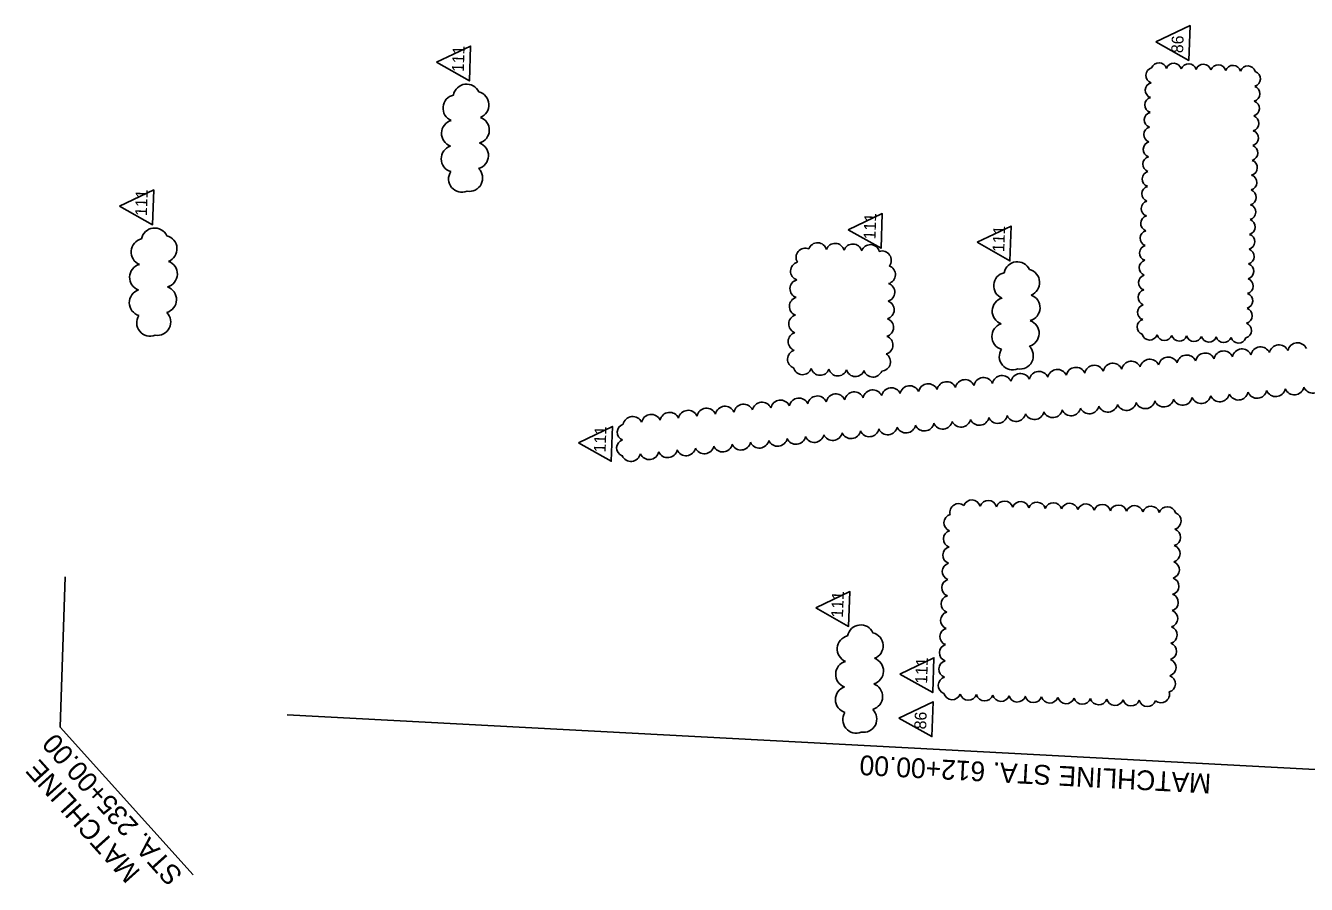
# Model space of a CAD drawing. Extents: x 928669 to 929521, y 636891 to 638153.
# Drawn here: x 928669 to 929187, y 636993 to 637341 of the extents above; entities that cross this region are included whole.
import ezdxf

# ---------------------------------------------------------------- set-up
doc = ezdxf.new("R2010")
doc.units = 0
doc.layers.add('Cloud_dp', color=7, linetype='Continuous')
doc.layers.add('MatchLines_dp', color=7, linetype='Continuous')

msp = doc.modelspace()

# ---------------------------------------------------------------- linework, layer by layer
at = {"layer": 'Cloud_dp'}
for points in [[(929126.34, 637333.99), (929139.65, 637326.48), (929140.14, 637340.55)], [(928835.21, 637325.69), (928848.52, 637318.18), (928849.01, 637332.25)], [(928706.97, 637267.46), (928720.28, 637259.95), (928720.77, 637274.02)], [(929001.81, 637257.92), (929015.12, 637250.41), (929015.62, 637264.49)], [(929053.95, 637252.83), (929067.26, 637245.32), (929067.75, 637259.4)], [(928892.62, 637171.72), (928905.92, 637164.21), (928906.42, 637178.28)], [(928988.69, 637104.86), (929001.99, 637097.34), (929002.49, 637111.42)], [(929022.71, 637078.07), (929036.02, 637070.56), (929036.51, 637084.63)], [(929022.35, 637060.26), (929035.66, 637052.75), (929036.15, 637066.82)]]:
    msp.add_lwpolyline(points, close=True, dxfattribs=at)
for centre, radius, start, end in [((929125.44, 637320.39), 3.15, 105.054, 250.054), ((929127.58, 637322.38), 3.14, 15.4978, 160.4978), ((929133.57, 637322.17), 3.14, 15.4978, 160.4978), ((929139.56, 637321.96), 3.14, 15.4978, 160.4978), ((929145.55, 637321.75), 3.14, 15.4978, 160.4978), ((929151.55, 637321.54), 3.14, 15.4978, 160.4978), ((929157.54, 637321.33), 3.14, 15.4978, 160.4978), ((929163.53, 637321.12), 3.14, 15.4978, 160.4978), ((929165.51, 637319), 3.14, 285.4978, 70.4978), ((928847.38, 637311.45), 5.42, 24.5019, 169.5019), ((929125.2, 637314.4), 3.14, 105.4978, 250.4978), ((928843.24, 637307.15), 5.42, 102.6495, 247.6495), ((928851.01, 637308.43), 5.42, 291.0688, 76.0688), ((929165.3, 637313), 3.14, 285.4978, 70.4978), ((929125, 637308.41), 3.14, 105.4978, 250.4978), ((929165.09, 637307.01), 3.14, 285.4978, 70.4978), ((928842.64, 637296.91), 5.42, 105.565, 250.565), ((928851.15, 637298.26), 5.42, 285.576, 70.576), ((929124.79, 637302.42), 3.14, 105.4978, 250.4978), ((929164.88, 637301.02), 3.14, 285.4978, 70.4978), ((929124.58, 637296.43), 3.14, 105.4978, 250.4978), ((929164.67, 637295.03), 3.14, 285.4978, 70.4978), ((928842.52, 637286.64), 5.42, 108.172, 253.172), ((928850.8, 637287.92), 5.42, 285.4978, 70.4978), ((929124.37, 637290.44), 3.14, 105.4978, 250.4978), ((929164.46, 637289.04), 3.14, 285.4978, 70.4978), ((929124.16, 637284.45), 3.14, 105.4978, 250.4978), ((929164.25, 637283.05), 3.14, 285.4978, 70.4978), ((928845.51, 637278.5), 5.42, 147.1328, 292.1328), ((928848.44, 637278.83), 5.42, 260.4905, 45.4905), ((929123.95, 637278.46), 3.14, 105.4978, 250.4978), ((929123.74, 637272.46), 3.14, 105.4978, 250.4978), ((929164.04, 637277.06), 3.14, 285.4978, 70.4978), ((929163.83, 637271.07), 3.14, 285.4978, 70.4978), ((929123.53, 637266.47), 3.14, 105.4978, 250.4978), ((929163.62, 637265.08), 3.14, 285.4978, 70.4978), ((929123.32, 637260.48), 3.14, 105.4978, 250.4978), ((929163.41, 637259.08), 3.14, 285.4978, 70.4978), ((928721.14, 637253.2), 5.42, 24.5019, 169.5019), ((928724.77, 637250.18), 5.42, 291.0688, 76.0688), ((929123.11, 637254.49), 3.14, 105.4978, 250.4978), ((929163.2, 637253.09), 3.14, 285.4978, 70.4978), ((928717.01, 637248.9), 5.42, 102.6495, 247.6495), ((928984.42, 637246.71), 3.74, 66.735, 211.735), ((928989.42, 637248.9), 3.74, 15.4978, 160.4978), ((928996.55, 637248.65), 3.74, 15.4978, 160.4978), ((929003.67, 637248.4), 3.74, 15.4978, 160.4978), ((929010.8, 637248.15), 3.74, 15.4978, 160.4978), ((929015.49, 637245.58), 3.74, 321.8977, 106.8977), ((929122.9, 637248.5), 3.14, 105.4978, 250.4978), ((929162.99, 637247.1), 3.14, 285.4978, 70.4978), ((928724.91, 637240.01), 5.42, 285.576, 70.576), ((928982.23, 637241.14), 3.74, 105.4978, 250.4978), ((929070.25, 637239.53), 5.42, 24.5019, 169.5019), ((929122.69, 637242.51), 3.14, 105.4978, 250.4978), ((928716.4, 637238.66), 5.42, 105.565, 250.565), ((929017.18, 637239.75), 3.74, 285.4978, 70.4978), ((929066.11, 637235.23), 5.42, 102.6495, 247.6495), ((929073.87, 637236.52), 5.42, 291.0688, 76.0688), ((929122.48, 637236.52), 3.14, 105.4978, 250.4978), ((929162.78, 637241.11), 3.14, 285.4978, 70.4978), ((928724.56, 637229.67), 5.42, 285.4978, 70.4978), ((928981.99, 637234.02), 3.74, 105.4978, 250.4978), ((929016.93, 637232.62), 3.74, 285.4978, 70.4978), ((929162.57, 637235.12), 3.14, 285.4978, 70.4978), ((928716.29, 637228.39), 5.42, 108.172, 253.172), ((928981.74, 637226.89), 3.74, 105.4978, 250.4978), ((929016.68, 637225.49), 3.74, 285.4978, 70.4978), ((929065.51, 637224.99), 5.42, 105.565, 250.565), ((929074.02, 637226.34), 5.42, 285.576, 70.576), ((929122.27, 637230.53), 3.14, 105.4978, 250.4978), ((929162.37, 637229.13), 3.14, 285.4978, 70.4978), ((928722.21, 637220.58), 5.42, 260.4905, 45.4905), ((929122.06, 637224.53), 3.14, 105.4978, 250.4978), ((929162.16, 637223.14), 3.14, 285.4978, 70.4978), ((928719.27, 637220.25), 5.42, 147.1328, 292.1328), ((928981.49, 637219.76), 3.74, 105.4978, 250.4978), ((929016.43, 637218.36), 3.74, 285.4978, 70.4978), ((929065.39, 637214.72), 5.42, 108.172, 253.172), ((929073.67, 637216), 5.42, 285.4978, 70.4978), ((929121.85, 637218.54), 3.14, 105.4978, 250.4978), ((929161.92, 637217.15), 3.15, 285.054, 70.054), ((928981.24, 637212.63), 3.74, 105.4978, 250.4978), ((929016.19, 637211.24), 3.74, 285.4978, 70.4978), ((929123.83, 637216.42), 3.14, 195.4978, 340.4978), ((929129.82, 637216.21), 3.14, 195.4978, 340.4978), ((929135.82, 637216), 3.14, 195.4978, 340.4978), ((929141.81, 637215.79), 3.14, 195.4978, 340.4978), ((929147.8, 637215.58), 3.14, 195.4978, 340.4978), ((929153.79, 637215.37), 3.14, 195.4978, 340.4978), ((929159.78, 637215.16), 3.14, 195.4978, 340.4978), ((928980.99, 637205.51), 3.74, 105.4978, 250.4978), ((929068.38, 637206.59), 5.42, 147.1328, 292.1328), ((929071.31, 637206.91), 5.42, 260.4905, 45.4905), ((929146.27, 637204.08), 3.94, 23.8283, 168.8283), ((929153.74, 637204.91), 3.94, 23.8283, 168.8283), ((929161.22, 637205.74), 3.94, 23.8283, 168.8283), ((929168.69, 637206.57), 3.94, 23.8283, 168.8283), ((929176.16, 637207.4), 3.94, 23.8283, 168.8283), ((929183.63, 637208.23), 3.94, 23.8283, 168.8283), ((929015.19, 637204.47), 3.74, 272.8227, 57.8227), ((929101.43, 637199.11), 3.94, 23.8283, 168.8283), ((929108.91, 637199.94), 3.94, 23.8283, 168.8283), ((929116.38, 637200.77), 3.94, 23.8283, 168.8283), ((929123.85, 637201.6), 3.94, 23.8283, 168.8283), ((929131.32, 637202.43), 3.94, 23.8283, 168.8283), ((929138.8, 637203.26), 3.94, 23.8283, 168.8283), ((928983.34, 637202.98), 3.74, 195.4978, 340.4978), ((928990.47, 637202.73), 3.74, 195.4978, 340.4978), ((928997.6, 637202.48), 3.74, 195.4978, 340.4978), ((929004.73, 637202.23), 3.74, 195.4978, 340.4978), ((929011.85, 637201.98), 3.74, 195.4978, 340.4978), ((929056.6, 637194.14), 3.94, 23.8283, 168.8283), ((929064.07, 637194.97), 3.94, 23.8283, 168.8283), ((929071.54, 637195.8), 3.94, 23.8283, 168.8283), ((929079.01, 637196.63), 3.94, 23.8283, 168.8283), ((929086.49, 637197.45), 3.94, 23.8283, 168.8283), ((929093.96, 637198.28), 3.94, 23.8283, 168.8283), ((929011.76, 637189.17), 3.94, 23.8283, 168.8283), ((929019.23, 637190), 3.94, 23.8283, 168.8283), ((929026.71, 637190.82), 3.94, 23.8283, 168.8283), ((929034.18, 637191.65), 3.94, 23.8283, 168.8283), ((929041.65, 637192.48), 3.94, 23.8283, 168.8283), ((929049.12, 637193.31), 3.94, 23.8283, 168.8283), ((929167.28, 637193.65), 3.97, 202.7882, 347.7882), ((929174.82, 637194.34), 3.97, 202.7882, 347.7882), ((929182.36, 637195.04), 3.97, 202.7882, 347.7882), ((929189.9, 637195.74), 3.97, 202.7882, 347.7882), ((928959.45, 637183.37), 3.94, 23.8283, 168.8283), ((928966.92, 637184.19), 3.94, 23.8283, 168.8283), ((928974.4, 637185.02), 3.94, 23.8283, 168.8283), ((928981.87, 637185.85), 3.94, 23.8283, 168.8283), ((928989.34, 637186.68), 3.94, 23.8283, 168.8283), ((928996.81, 637187.51), 3.94, 23.8283, 168.8283), ((929004.29, 637188.34), 3.94, 23.8283, 168.8283), ((929106.94, 637188.06), 3.97, 202.7882, 347.7882), ((929114.48, 637188.76), 3.97, 202.7882, 347.7882), ((929122.02, 637189.46), 3.97, 202.7882, 347.7882), ((929129.57, 637190.15), 3.97, 202.7882, 347.7882), ((929137.11, 637190.85), 3.97, 202.7882, 347.7882), ((929144.65, 637191.55), 3.97, 202.7882, 347.7882), ((929152.19, 637192.25), 3.97, 202.7882, 347.7882), ((929159.73, 637192.95), 3.97, 202.7882, 347.7882), ((928914.61, 637178.39), 3.94, 23.8283, 168.8283), ((928922.09, 637179.22), 3.94, 23.8283, 168.8283), ((928929.56, 637180.05), 3.94, 23.8283, 168.8283), ((928937.03, 637180.88), 3.94, 23.8283, 168.8283), ((928944.5, 637181.71), 3.94, 23.8283, 168.8283), ((928951.98, 637182.54), 3.94, 23.8283, 168.8283), ((929062.33, 637183.45), 3.91, 203.4337, 348.4337), ((929069.76, 637184.22), 3.91, 203.4337, 348.4337), ((929077.18, 637184.99), 3.91, 203.4337, 348.4337), ((929084.6, 637185.76), 3.91, 203.4337, 348.4337), ((929092.02, 637186.54), 3.91, 203.4337, 348.4337), ((929099.44, 637187.31), 3.91, 203.4337, 348.4337), ((928911.64, 637175.95), 3.33, 105.4978, 250.4978), ((929010.38, 637178.05), 3.91, 203.4337, 348.4337), ((929017.8, 637178.82), 3.91, 203.4337, 348.4337), ((929025.22, 637179.59), 3.91, 203.4337, 348.4337), ((929032.65, 637180.36), 3.91, 203.4337, 348.4337), ((929040.07, 637181.14), 3.91, 203.4337, 348.4337), ((929047.49, 637181.91), 3.91, 203.4337, 348.4337), ((929054.91, 637182.68), 3.91, 203.4337, 348.4337), ((928911.41, 637169.6), 3.33, 105.4978, 250.4978), ((928958.42, 637172.65), 3.91, 203.4337, 348.4337), ((928965.85, 637173.42), 3.91, 203.4337, 348.4337), ((928973.27, 637174.19), 3.91, 203.4337, 348.4337), ((928980.69, 637174.96), 3.91, 203.4337, 348.4337), ((928988.11, 637175.74), 3.91, 203.4337, 348.4337), ((928995.54, 637176.51), 3.91, 203.4337, 348.4337), ((929002.96, 637177.28), 3.91, 203.4337, 348.4337), ((928913.89, 637168.02), 3.91, 203.4337, 348.4337), ((928921.31, 637168.79), 3.91, 203.4337, 348.4337), ((928928.74, 637169.56), 3.91, 203.4337, 348.4337), ((928936.16, 637170.34), 3.91, 203.4337, 348.4337), ((928943.58, 637171.11), 3.91, 203.4337, 348.4337), ((928951, 637171.88), 3.91, 203.4337, 348.4337), ((929046.42, 637143.59), 3.45, 50.5616, 195.5616), ((929051.87, 637145.1), 3.46, 15.4978, 160.4978), ((929058.46, 637144.87), 3.46, 15.4978, 160.4978), ((929065.05, 637144.64), 3.46, 15.4978, 160.4978), ((929071.64, 637144.41), 3.46, 15.4978, 160.4978), ((929078.22, 637144.18), 3.46, 15.4978, 160.4978), ((929084.81, 637143.95), 3.46, 15.4978, 160.4978), ((929091.4, 637143.72), 3.46, 15.4978, 160.4978), ((929097.99, 637143.49), 3.46, 15.4978, 160.4978), ((929104.58, 637143.26), 3.46, 15.4978, 160.4978), ((929111.16, 637143.03), 3.46, 15.4978, 160.4978), ((929117.75, 637142.8), 3.46, 15.4978, 160.4978), ((929124.34, 637142.57), 3.46, 15.4978, 160.4978), ((929130.93, 637142.34), 3.46, 15.4978, 160.4978), ((929044.02, 637139.33), 3.46, 105.4978, 250.4978), ((929133.1, 637140.01), 3.46, 285.4978, 70.4978), ((929043.79, 637132.74), 3.46, 105.4978, 250.4978), ((929132.87, 637133.42), 3.46, 285.4978, 70.4978), ((929043.56, 637126.16), 3.46, 105.4978, 250.4978), ((929132.64, 637126.83), 3.46, 285.4978, 70.4978), ((929043.33, 637119.57), 3.46, 105.4978, 250.4978), ((929132.41, 637120.24), 3.46, 285.4978, 70.4978), ((929043.1, 637112.98), 3.46, 105.4978, 250.4978), ((929132.18, 637113.65), 3.46, 285.4978, 70.4978), ((929042.87, 637106.39), 3.46, 105.4978, 250.4978), ((929131.95, 637107.07), 3.46, 285.4978, 70.4978), ((929042.64, 637099.81), 3.46, 105.4978, 250.4978), ((929131.72, 637100.48), 3.46, 285.4978, 70.4978), ((929006.91, 637092.52), 5.42, 24.5019, 169.5019), ((929010.53, 637089.5), 5.42, 291.0688, 76.0688), ((929042.41, 637093.22), 3.46, 105.4978, 250.4978), ((929131.49, 637093.89), 3.46, 285.4978, 70.4978), ((929002.77, 637088.21), 5.42, 102.6495, 247.6495), ((929042.17, 637086.63), 3.46, 105.4978, 250.4978), ((929131.26, 637087.3), 3.46, 285.4978, 70.4978), ((929010.68, 637079.32), 5.42, 285.576, 70.576), ((929131.03, 637080.71), 3.46, 285.4978, 70.4978), ((929002.16, 637077.97), 5.42, 105.565, 250.565), ((929041.94, 637080.04), 3.46, 105.4978, 250.4978), ((929010.32, 637068.99), 5.42, 285.4978, 70.4978), ((929041.71, 637073.45), 3.46, 105.4978, 250.4978), ((929130.8, 637074.13), 3.46, 285.4978, 70.4978), ((929002.05, 637067.7), 5.42, 108.172, 253.172), ((929043.89, 637071.12), 3.46, 195.4978, 340.4978), ((929050.48, 637070.89), 3.46, 195.4978, 340.4978), ((929057.07, 637070.66), 3.46, 195.4978, 340.4978), ((929063.65, 637070.43), 3.46, 195.4978, 340.4978), ((929070.24, 637070.2), 3.46, 195.4978, 340.4978), ((929076.83, 637069.97), 3.46, 195.4978, 340.4978), ((929083.42, 637069.74), 3.46, 195.4978, 340.4978), ((929090.01, 637069.51), 3.46, 195.4978, 340.4978), ((929096.59, 637069.28), 3.46, 195.4978, 340.4978), ((929103.18, 637069.05), 3.46, 195.4978, 340.4978), ((929128.4, 637069.87), 3.45, 230.5616, 15.5616), ((929007.97, 637059.89), 5.42, 260.4905, 45.4905), ((929109.77, 637068.82), 3.46, 195.4978, 340.4978), ((929116.36, 637068.59), 3.46, 195.4978, 340.4978), ((929122.94, 637068.36), 3.46, 195.4978, 340.4978), ((929005.03, 637059.57), 5.42, 147.1328, 292.1328)]:
    msp.add_arc(centre, radius, start, end, dxfattribs=at)
at = {"layer": 'MatchLines_dp'}
for p, q in [((928682.87, 637056.6), (928684.89, 637117.41)), ((928736.73, 636996.72), (928682.87, 637056.6))]:
    msp.add_line(p, q, dxfattribs=at)
msp.add_lwpolyline([(929426.17, 637026.85), (929066.68, 637046.02), (928774.81, 637061.58)], dxfattribs=at)

# ---------------------------------------------------------------- texts
at = {"layer": 'Cloud_dp'}
for s, p in [('86', (929137.33, 637329.34)), ('111', (928846.23, 637321.67)), ('111', (928717.99, 637263.44)), ('111', (929012.83, 637253.9)), ('111', (929064.97, 637248.82)), ('111', (928903.63, 637167.7)), ('111', (928999.7, 637100.84)), ('111', (929033.73, 637074.05)), ('86', (929033.34, 637055.61))]:
    msp.add_text(s, height=4.8, rotation=87.9978, dxfattribs=at).set_placement(p)
at = {"layer": 'MatchLines_dp'}
for s, rotation, p in [('STA. 235+00.00', 131.9666, (928732.88, 636996.98)), ('MATCHLINE', 131.9666, (928715.75, 636998.08)), ('MATCHLINE STA. 612+00.00', 176.9478, (929148.86, 637037.63))]:
    msp.add_text(s, height=8, rotation=rotation, dxfattribs=at).set_placement(p)

doc.saveas('drawing.dxf')
